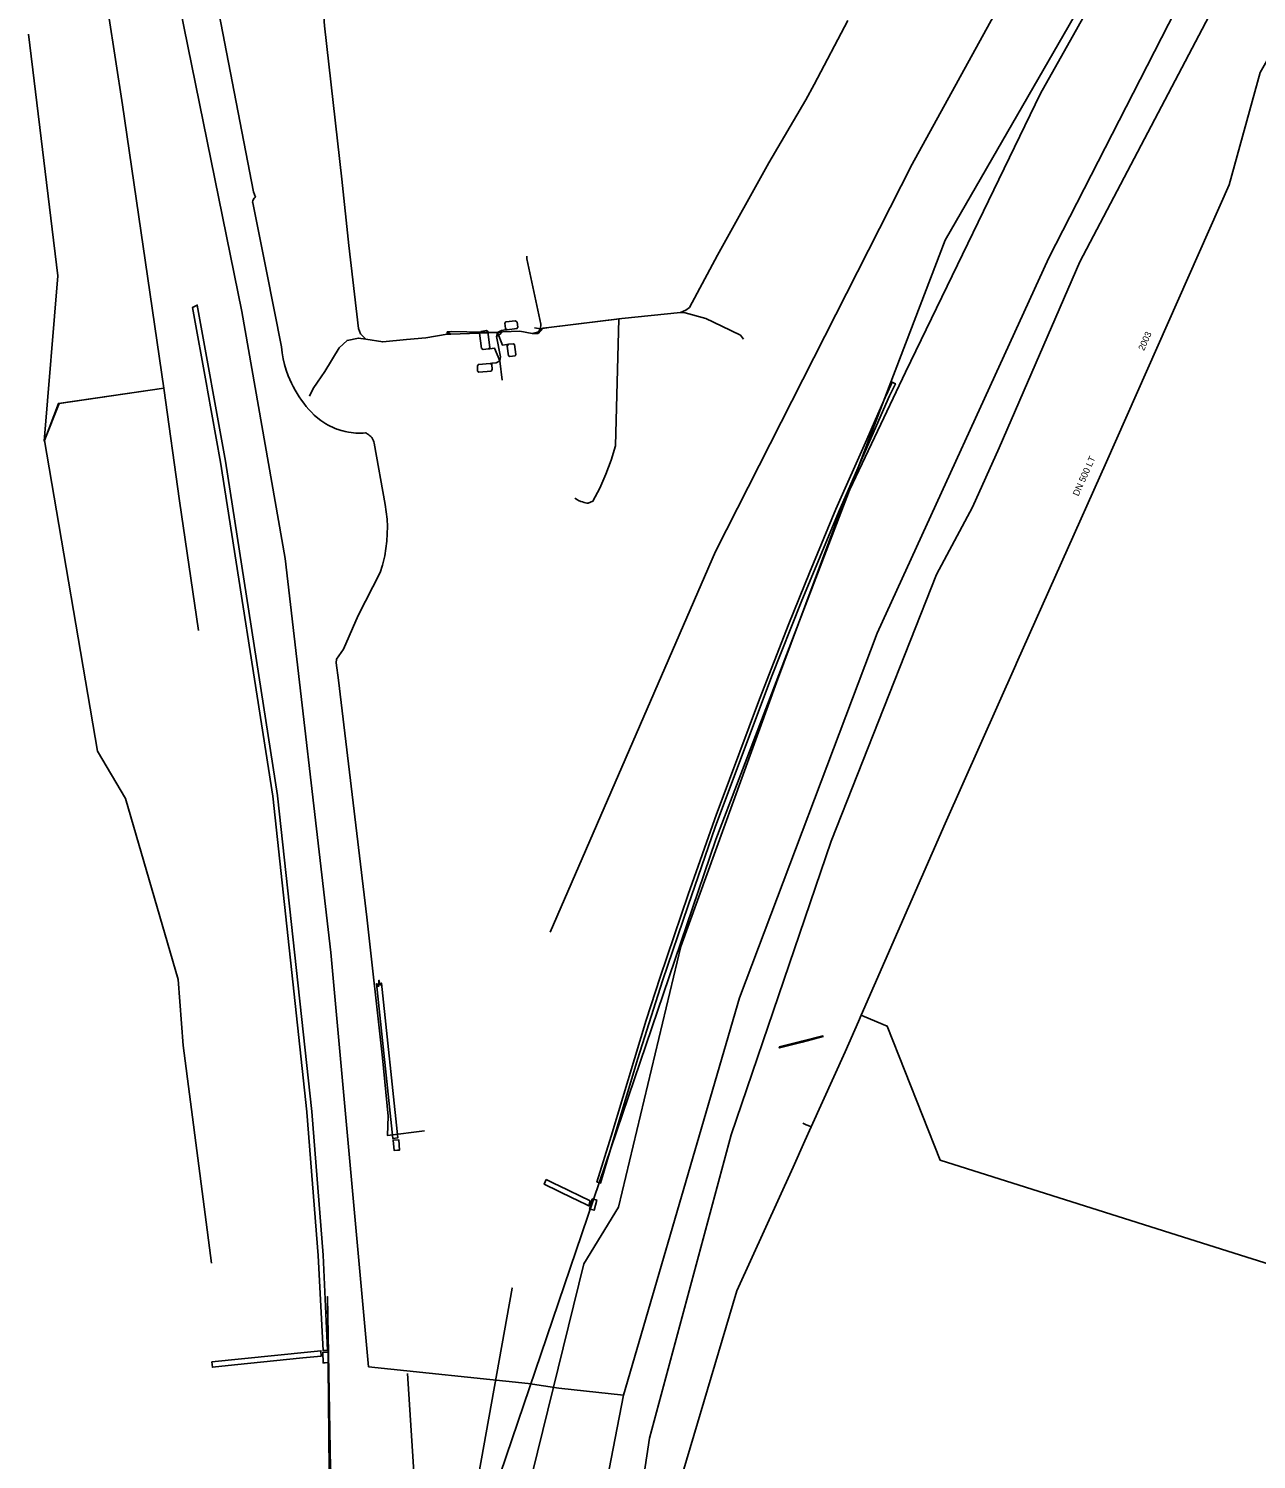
# Model space of a CAD drawing. Extents: x -599951 to -598963, y -1164095 to -1162939.
# Drawn here: x -599200.3 to -599050.3, y -1163616.2 to -1163441.6 of the extents above; entities that cross this region are included whole.
import ezdxf

# ---------------------------------------------------------------- set-up
doc = ezdxf.new("R2010")
doc.units = 0
for name, color, linetype in [('Level 1', 7, 'Continuous'), ('Level 3', 7, 'Continuous'), ('Vrstva 1', 7, 'Continuous'), ('Vrstva 13', 7, 'Continuous'), ('Vrstva 15', 7, 'Continuous'), ('Vrstva 42', 7, 'Continuous'), ('Vrstva 55', 7, 'Continuous')]:
    doc.layers.add(name, color=color, linetype=linetype)

msp = doc.modelspace()

# ---------------------------------------------------------------- linework, layer by layer
at = {"layer": 'Level 1'}
msp.add_lwpolyline([(-599173.8, -1163822.04), (-599166.01, -1163726.36), (-599144.8, -1163624.27), (-599116.33, -1163540.56), (-599088.36, -1163467.42), (-599053.62, -1163407.24), (-599018.44, -1163353.97), (-598979.36, -1163301.03), (-598963.215, -1163275.716)], dxfattribs=at)
at = {"layer": 'Level 3'}
for points in [[(-599178.488, -1163485.266), (-599180.23, -1163475.637), (-599179.672, -1163475.348), (-599176.227, -1163494.394), (-599169.854, -1163535.218), (-599169.853, -1163535.224), (-599165.68, -1163573.775), (-599165.679, -1163573.782), (-599164.3, -1163591.294), (-599163.744, -1163602.929), (-599164.305, -1163602.95), (-599164.899, -1163591.341), (-599166.278, -1163573.829), (-599166.278, -1163573.825), (-599170.45, -1163535.292), (-599176.817, -1163494.504), (-599178.4, -1163485.754), (-599178.488, -1163485.266), (-599180.23, -1163475.637)], [(-599124.843, -1163562.635), (-599123.135, -1163557.358), (-599119.726, -1163547.29), (-599116.259, -1163537.5), (-599115.93, -1163536.632), (-599110.999, -1163523.45), (-599107.428, -1163514.266), (-599104.907, -1163508.022), (-599101.674, -1163500.271), (-599097.921, -1163491.738), (-599096.851, -1163489.314), (-599095.658, -1163486.618), (-599095.524, -1163486.317), (-599094.817, -1163484.773), (-599094.422, -1163484.942), (-599095.129, -1163486.425), (-599101.288, -1163500.458), (-599105.939, -1163511.619), (-599109.544, -1163520.722), (-599116.417, -1163539.07), (-599119.736, -1163548.624), (-599122.846, -1163557.824), (-599125.866, -1163567.314), (-599128.761, -1163576.91), (-599130.416, -1163582.501), (-599130.635, -1163582.446), (-599130.855, -1163582.378), (-599129.132, -1163576.793)], [(-599157.552, -1163558.55), (-599157.478, -1163557.74), (-599157.331, -1163558.329), (-599157.172, -1163558.099), (-599155.18, -1163577), (-599155.775, -1163577.069), (-599157.768, -1163558.161)], [(-599103.273, -1163564.513), (-599103.242, -1163564.63), (-599105.82, -1163565.297), (-599108.562, -1163566.006), (-599108.597, -1163565.89), (-599105.861, -1163565.182)], [(-599155.216, -1163578.488), (-599155.64, -1163578.52), (-599155.76, -1163577.26), (-599155.064, -1163577.208), (-599154.97, -1163578.47)], [(-599137.06, -1163582.064), (-599135.994, -1163582.585), (-599135.543, -1163582.806), (-599131.705, -1163584.683), (-599131.864, -1163585.294), (-599133.36, -1163584.562), (-599133.809, -1163584.343), (-599137.293, -1163582.639)], [(-599131.382, -1163585.78), (-599131.682, -1163585.698), (-599131.757, -1163585.678), (-599131.435, -1163584.436), (-599131.267, -1163584.48), (-599130.88, -1163584.58), (-599131.204, -1163585.829)], [(-599177.873, -1163604.333), (-599166.22, -1163603.13), (-599164.56, -1163602.96), (-599164.534, -1163603.611), (-599166.775, -1163603.843), (-599175.108, -1163604.703), (-599177.806, -1163604.981)], [(-599163.68, -1163603.13), (-599163.63, -1163604.42), (-599164.036, -1163604.436), (-599164.301, -1163604.446), (-599164.35, -1163603.17)]]:
    msp.add_lwpolyline(points, close=True, dxfattribs=at)
at = {"layer": 'Vrstva 1'}
for p, q in [((-599092.39, -1163458.16), (-599066.79, -1163411.69)), ((-599075.69, -1163469.57), (-599052.71, -1163424.78)), ((-599181.75, -1163439.17), (-599174.22, -1163476.13)), ((-599116.39, -1163505.42), (-599092.39, -1163458.16)), ((-599096.63, -1163515.38), (-599075.69, -1163469.57)), ((-599174.22, -1163476.13), (-599168.93, -1163506.28)), ((-599168.93, -1163506.28), (-599163.34, -1163554.38)), ((-599136.57, -1163551.88), (-599116.39, -1163505.42)), ((-599113.46, -1163559.9), (-599096.63, -1163515.38)), ((-599163.34, -1163554.38), (-599158.76, -1163604.92)), ((-599127.62, -1163608.39), (-599113.46, -1163559.9)), ((-599158.76, -1163604.92), (-599139.25, -1163606.98)), ((-599139.25, -1163606.98), (-599135.5, -1163607.53)), ((-599135.5, -1163607.53), (-599127.62, -1163608.39)), ((-599137.27, -1163657.85), (-599127.62, -1163608.39))]:
    msp.add_line(p, q, dxfattribs=at)
at = {"layer": 'Vrstva 13'}
for p, q in [((-599105.306, -1163575.386), (-599105.741, -1163575.189)), ((-599105.074, -1163575.488), (-599105.306, -1163575.386)), ((-599104.714, -1163575.654), (-599105.074, -1163575.488))]:
    msp.add_line(p, q, dxfattribs=at)
for points in [[(-599033.69, -1163418.68), (-599049.89, -1163446.95), (-599053.65, -1163460.69), (-599068.65, -1163494.5), (-599079.623, -1163519.036), (-599079.73, -1163519.27), (-599088.36, -1163538.62), (-599098.581, -1163562.017), (-599098.91, -1163562.77), (-599100.57, -1163566.48), (-599104.714, -1163575.654), (-599105.48, -1163577.35), (-599106.92, -1163580.56), (-599113.79, -1163595.64), (-599122.631, -1163625.369), (-599122.71, -1163625.62), (-599132.883, -1163657.941), (-599133.15, -1163658.79), (-599136.279, -1163681.357), (-599143.211, -1163745.819)], [(-599098.581, -1163562.017), (-599098.23, -1163562.17), (-599095.42, -1163563.35), (-599088.95, -1163579.72), (-599058.45, -1163589.35), (-599043.23, -1163594.15), (-599038.702, -1163580.228)]]:
    msp.add_lwpolyline(points, dxfattribs=at)
at = {"layer": 'Vrstva 42'}
for p, q in [((-599149.165, -1163478.62), (-599149.135, -1163478.915)), ((-599149.165, -1163478.62), (-599149.135, -1163478.915)), ((-599148.71, -1163478.9), (-599149.135, -1163478.915)), ((-599143.02, -1163478.7), (-599143.115, -1163479.165)), ((-599143.02, -1163478.7), (-599143.115, -1163479.165)), ((-599142.72, -1163482.15), (-599142.45, -1163484.5)), ((-599142.72, -1163482.15), (-599142.45, -1163484.5))]:
    msp.add_line(p, q, dxfattribs=at)
for points in [[(-599159.08, -1163479.49), (-599159.72, -1163478.87), (-599159.98, -1163478.2), (-599161.14, -1163468.08), (-599162, -1163459.97), (-599164.11, -1163441.27), (-599164.4, -1163437.31)], [(-599159.08, -1163479.49), (-599159.72, -1163478.87), (-599159.98, -1163478.2), (-599161.14, -1163468.08), (-599162, -1163459.97), (-599164.11, -1163441.27), (-599164.4, -1163437.31)], [(-599142.6, -1163478.8), (-599142.39, -1163478.61), (-599140.28, -1163478.55), (-599138.78, -1163478.81), (-599138.13, -1163478.66), (-599137.75, -1163478.23), (-599137.7, -1163477.69), (-599139.41, -1163469.72), (-599139.43, -1163469.37)], [(-599142.39, -1163478.61), (-599140.28, -1163478.55), (-599138.78, -1163478.81), (-599138.13, -1163478.66), (-599137.75, -1163478.23), (-599137.7, -1163477.69), (-599139.41, -1163469.72), (-599139.43, -1163469.37)], [(-599120.65, -1163476.27), (-599127.81, -1163476.98), (-599136.73, -1163478.07), (-599137.467, -1163478.174)], [(-599112.95, -1163479.49), (-599113.35, -1163479.02), (-599115.6, -1163477.93), (-599117.55, -1163476.97), (-599120.07, -1163476.31), (-599120.65, -1163476.27)], [(-599149.135, -1163478.915), (-599151.76, -1163479.35), (-599154.1, -1163479.57), (-599157.01, -1163479.84), (-599159.08, -1163479.49)], [(-599149.135, -1163478.915), (-599151.76, -1163479.35), (-599154.1, -1163479.57), (-599157.01, -1163479.84), (-599159.08, -1163479.49)], [(-599149.165, -1163478.62), (-599148.64, -1163478.58), (-599142.98, -1163478.68), (-599142.39, -1163478.61)], [(-599149.165, -1163478.62), (-599148.71, -1163478.9), (-599142.98, -1163478.68), (-599142.39, -1163478.61)], [(-599142.72, -1163482.15), (-599143.36, -1163480.62), (-599143.95, -1163480.68), (-599143.96, -1163480.55), (-599144.18, -1163478.57), (-599144.35, -1163478.46), (-599145, -1163478.56), (-599145.19, -1163478.78), (-599144.96, -1163480.63), (-599144.77, -1163480.77)], [(-599142.6, -1163478.8), (-599143.115, -1163479.165), (-599142.63, -1163481.68), (-599142.72, -1163482.15)], [(-599143.02, -1163478.7), (-599142.53, -1163478.46), (-599142.01, -1163478.39), (-599141.84, -1163478.36), (-599140.64, -1163478.22), (-599140.53, -1163478.06), (-599140.59, -1163477.45), (-599140.79, -1163477.28), (-599142, -1163477.4), (-599142.11, -1163477.56)], [(-599143.02, -1163478.7), (-599142.39, -1163480.25), (-599141.86, -1163480.17), (-599141.82, -1163480.35), (-599141.65, -1163481.54), (-599141.51, -1163481.63), (-599140.85, -1163481.54), (-599140.76, -1163481.38), (-599140.94, -1163480.16), (-599141.09, -1163480.07)], [(-599142.01, -1163478.39), (-599142.03, -1163478.21), (-599142.11, -1163477.56)], [(-599141.84, -1163478.36), (-599142.03, -1163478.21)], [(-599138.78, -1163478.81), (-599138.03, -1163478.81)], [(-599138.029, -1163478.81), (-599137.467, -1163478.174)], [(-599159.08, -1163479.49), (-599159.99, -1163479.38), (-599161.38, -1163479.66), (-599162.34, -1163480.56), (-599164.07, -1163483.44), (-599165, -1163484.77), (-599165.51, -1163485.55), (-599165.97, -1163486.47)], [(-599143.96, -1163480.55), (-599144.09, -1163480.7)], [(-599143.115, -1163479.165), (-599142.63, -1163481.68), (-599142.72, -1163482.15)], [(-599141.86, -1163480.17), (-599141.67, -1163480.14), (-599141.09, -1163480.07)], [(-599141.82, -1163480.35), (-599141.67, -1163480.14)], [(-599142.72, -1163482.15), (-599143.15, -1163482.4), (-599143.71, -1163482.45), (-599143.89, -1163482.46), (-599145.33, -1163482.6), (-599145.45, -1163482.76), (-599145.43, -1163483.4), (-599145.28, -1163483.52), (-599143.78, -1163483.41), (-599143.65, -1163483.21)], [(-599143.95, -1163480.68), (-599144.09, -1163480.7), (-599144.77, -1163480.77)], [(-599143.89, -1163482.46), (-599143.7, -1163482.6)], [(-599143.71, -1163482.45), (-599143.7, -1163482.6), (-599143.65, -1163483.21)]]:
    msp.add_lwpolyline(points, dxfattribs=at)
at = {"layer": 'Vrstva 55'}
for points in [[(-599056.04, -1163381.08), (-599054.78, -1163380.84), (-599043.79, -1163387.33), (-599020.488, -1163353.364), (-598995.31, -1163320.12), (-598993.82, -1163320.12), (-599016.324, -1163352.72), (-599037.484, -1163383.409), (-599040.79, -1163389.08), (-599058.044, -1163416.158), (-599062.52, -1163424.31), (-599076.715, -1163449.508), (-599093.194, -1163483.52), (-599100.75, -1163499.5), (-599108.949, -1163521.401), (-599120.598, -1163553.641), (-599128.23, -1163585.45), (-599132.47, -1163592.35), (-599141.869, -1163630.55), (-599150.024, -1163670.629), (-599149.47, -1163675.64), (-599149.011, -1163670.773)], [(-599183.74, -1163485.49), (-599188.79, -1163450.9), (-599190.5, -1163439.86), (-599192.07, -1163427.52), (-599193.88, -1163409.95), (-599196.91, -1163389.13), (-599198.044, -1163380.488)], [(-599056.04, -1163381.08), (-599030.274, -1163396.071), (-599035.081, -1163404.612), (-599055.684, -1163439.259), (-599071.88, -1163470.061), (-599081.76, -1163492.77)], [(-599177.96, -1163434.77), (-599172.809, -1163461.537)], [(-599100.21, -1163440.62), (-599104.349, -1163448.439), (-599105.34, -1163450.31), (-599109.87, -1163458.01), (-599116.14, -1163469.27), (-599119.57, -1163475.64), (-599120.01, -1163475.96), (-599120.65, -1163476.27), (-599127.81, -1163476.98), (-599136.73, -1163478.07), (-599137.75, -1163478.23), (-599138.472, -1163478.12)], [(-599183.74, -1163485.49), (-599196.52, -1163487.35), (-599198.35, -1163491.97), (-599196.7, -1163471.79), (-599200.26, -1163442.29)], [(-599172.809, -1163461.537), (-599172.56, -1163462.17), (-599172.632, -1163462.226), (-599172.697, -1163462.291), (-599172.802, -1163462.44), (-599172.871, -1163462.609), (-599172.901, -1163462.788), (-599172.9, -1163462.88), (-599171.218, -1163471.194), (-599169.38, -1163480.46), (-599169.29, -1163481.179), (-599169.162, -1163481.893), (-599168.996, -1163482.598), (-599168.791, -1163483.294), (-599168.549, -1163483.977), (-599168.368, -1163484.425), (-599168.17, -1163484.866), (-599167.957, -1163485.3), (-599167.728, -1163485.725), (-599167.484, -1163486.142), (-599167.225, -1163486.55), (-599166.952, -1163486.949), (-599166.664, -1163487.337), (-599166.363, -1163487.715), (-599166.048, -1163488.082), (-599165.72, -1163488.437), (-599165.38, -1163488.78), (-599164.931, -1163489.168), (-599164.576, -1163489.438), (-599164.331, -1163489.607), (-599164.081, -1163489.767), (-599163.954, -1163489.843), (-599163.695, -1163489.989), (-599163.432, -1163490.126), (-599163.163, -1163490.253), (-599162.891, -1163490.371), (-599162.614, -1163490.478), (-599162.474, -1163490.529), (-599162.113, -1163490.645), (-599161.906, -1163490.703), (-599161.618, -1163490.775), (-599161.182, -1163490.863), (-599160.888, -1163490.909), (-599160.593, -1163490.944), (-599160.297, -1163490.969), (-599159.868, -1163490.985), (-599159.555, -1163490.983), (-599159.407, -1163490.978), (-599159.11, -1163490.96), (-599159.012, -1163491), (-599158.917, -1163491.047), (-599158.825, -1163491.1), (-599158.708, -1163491.179), (-599158.573, -1163491.292), (-599158.474, -1163491.393), (-599158.363, -1163491.531), (-599158.268, -1163491.68), (-599158.219, -1163491.773), (-599158.163, -1163491.903), (-599158.119, -1163492.037), (-599158.08, -1163492.21), (-599156.72, -1163499.68), (-599156.582, -1163500.57), (-599156.492, -1163501.466), (-599156.452, -1163502.365), (-599156.46, -1163503.265), (-599156.517, -1163504.163), (-599156.622, -1163505.057), (-599156.776, -1163505.943), (-599157.055, -1163507.11), (-599157.32, -1163507.97), (-599160.01, -1163513.22), (-599161.81, -1163517.34), (-599162.68, -1163518.58), (-599162.69, -1163519), (-599162.41, -1163521.13), (-599158.96, -1163550.07), (-599157.05, -1163567.2), (-599156.37, -1163574.32), (-599156.424, -1163576.712), (-599151.927, -1163576.139)], [(-599138.472, -1163478.12), (-599137.75, -1163478.23), (-599136.73, -1163478.07), (-599128.449, -1163477.06), (-599128.201, -1163477.023), (-599128.61, -1163492.54), (-599129.127, -1163494.292), (-599129.758, -1163496.005), (-599130.5, -1163497.674), (-599131.35, -1163499.29), (-599131.95, -1163499.53), (-599132.1, -1163499.506), (-599132.249, -1163499.476), (-599132.439, -1163499.43), (-599132.616, -1163499.378), (-599132.832, -1163499.303), (-599133.112, -1163499.185), (-599133.249, -1163499.118), (-599133.45, -1163499.009), (-599133.58, -1163498.93)], [(-599183.74, -1163485.49), (-599196.62, -1163487.36), (-599198.31, -1163491.86), (-599191.85, -1163529.81), (-599188.439, -1163535.565), (-599182.01, -1163557.64), (-599181.4, -1163565.696), (-599177.923, -1163592.264)], [(-599183.74, -1163485.49), (-599181.845, -1163499.244), (-599179.511, -1163515.049)], [(-599081.76, -1163492.77), (-599085.01, -1163500.01), (-599089.419, -1163508.224), (-599102.253, -1163540.759), (-599114.485, -1163576.598), (-599124.443, -1163613.639), (-599126.99, -1163630.61)], [(-599167.231, -1163749.736), (-599164.09, -1163719.94), (-599163.502, -1163711.028), (-599161.82, -1163703.03), (-599149.662, -1163662.667), (-599149.9, -1163643.97), (-599149.72, -1163642.66), (-599141.225, -1163595.312), (-599149.72, -1163642.66), (-599150.889, -1163636.89), (-599151.042, -1163635.358), (-599152.176, -1163631.956), (-599152.636, -1163626.624), (-599153.984, -1163605.724)], [(-599175.395, -1163623.226), (-599162.201, -1163622.122), (-599162.465, -1163620.313), (-599163.569, -1163617.577), (-599163.745, -1163596.351), (-599163.392, -1163617.356), (-599162.156, -1163620.269), (-599161.81, -1163622.13), (-599160.56, -1163644.3), (-599158.79, -1163673), (-599157.055, -1163697.078), (-599156.945, -1163710.937), (-599156.578, -1163727.5), (-599157.054, -1163727.447)]]:
    msp.add_lwpolyline(points, dxfattribs=at)

# ---------------------------------------------------------------- texts
at = {"layer": 'Vrstva 15'}
for s, rotation, p in [('2003', 66.06203, (-599064.069, -1163480.989)), ('DN 500 LT', 65.89015, (-599072.079, -1163498.736))]:
    msp.add_text(s, height=0.8, rotation=rotation, dxfattribs=at).set_placement(p)

doc.saveas('drawing.dxf')
